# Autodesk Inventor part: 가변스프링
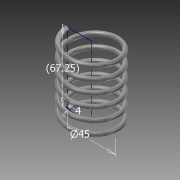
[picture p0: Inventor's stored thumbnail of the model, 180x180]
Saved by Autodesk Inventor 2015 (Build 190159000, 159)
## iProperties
Created: 2016-02
Part Number: 가변스프링
Material: 스테인레스 스틸
Document SubType Name: Modeling
Designer: Administrator
Density: 8 g/cm^3
Appearance: 반연마
Mass: 84.2127 g
Surface Area: 106.464 cm^2
Volume: 10.5266 cm^3
Author: Administrator
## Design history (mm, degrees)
sketch "스케치1"
  geometry: L1 (0, 0)-(0, 67.25); L2 (0, 67.25)-(22.5, 67.25); L3 (22.5, 67.25)-(22.5, 0); L4 (22.5, 0)-(0, 0); C1 r 2 at (22.5, 0)
  constraints: 8 end point, 3 perpendicular, 1 centre point, 1 coincident, 1 vertical
  dimensions: "d0" = 67.25 distance of L2.end L3.end (derived); "d1" = 45 diameter of L3 L1; "d2" = 4 diameter of C1
feature "코일1" sketch "스케치1" pitch "d3" = 10; turns "d5" = 6; dims "d4" = 67.25 (= d0), "d6" = 0, angle "d7" = 90 deg, angle "d8" = 90 deg, "d9" = 0, "d10" = 0
sketch "스케치2"
  geometry: L1 (-20.5, 0)-(-24.5, 0) reference; 1 further point
  constraints: 1 horizontal alignment
extrude "돌출1" cut sketch "스케치2" stored distance "d11" = 10; taper "d12" = 0 deg
node "작업 평면1"
sketch "스케치3"
  geometry: L1 (-24.5, 0)-(-20.5, 0) reference; 1 further point
  constraints: 1 horizontal alignment
extrude "돌출2" cut sketch "스케치3" stored distance "d13" = 10; taper "d14" = 0 deg
node "솔리드1"
node "절단 모서리 투영1"
node "절단 모서리 투영2"
